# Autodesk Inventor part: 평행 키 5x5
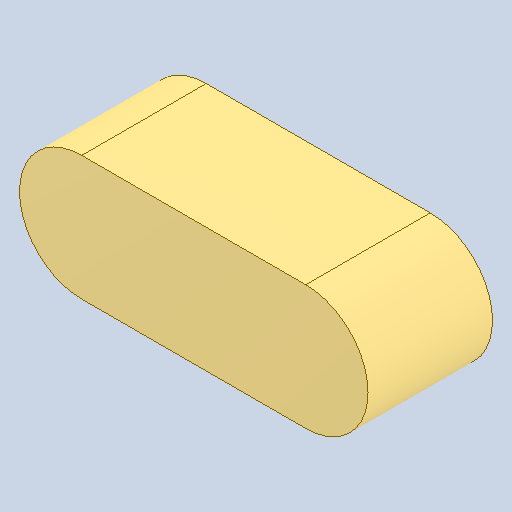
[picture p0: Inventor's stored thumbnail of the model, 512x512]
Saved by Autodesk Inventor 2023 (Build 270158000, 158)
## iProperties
Created: 2025-04
Part Number: 평행 키 5x5
Material: 강철, 연강
Document SubType Name: Modeling
Designer: ADMIN_PC
Density: 7.86 g/cm^3
Appearance: 기본값
Author: jhkim
Revision Number: 1
Sending System: Autodesk Inventor 2026
Preprocessor: ST-DEVELOPER v20.1
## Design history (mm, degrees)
feature "솔리드1"
node "솔리드2"
